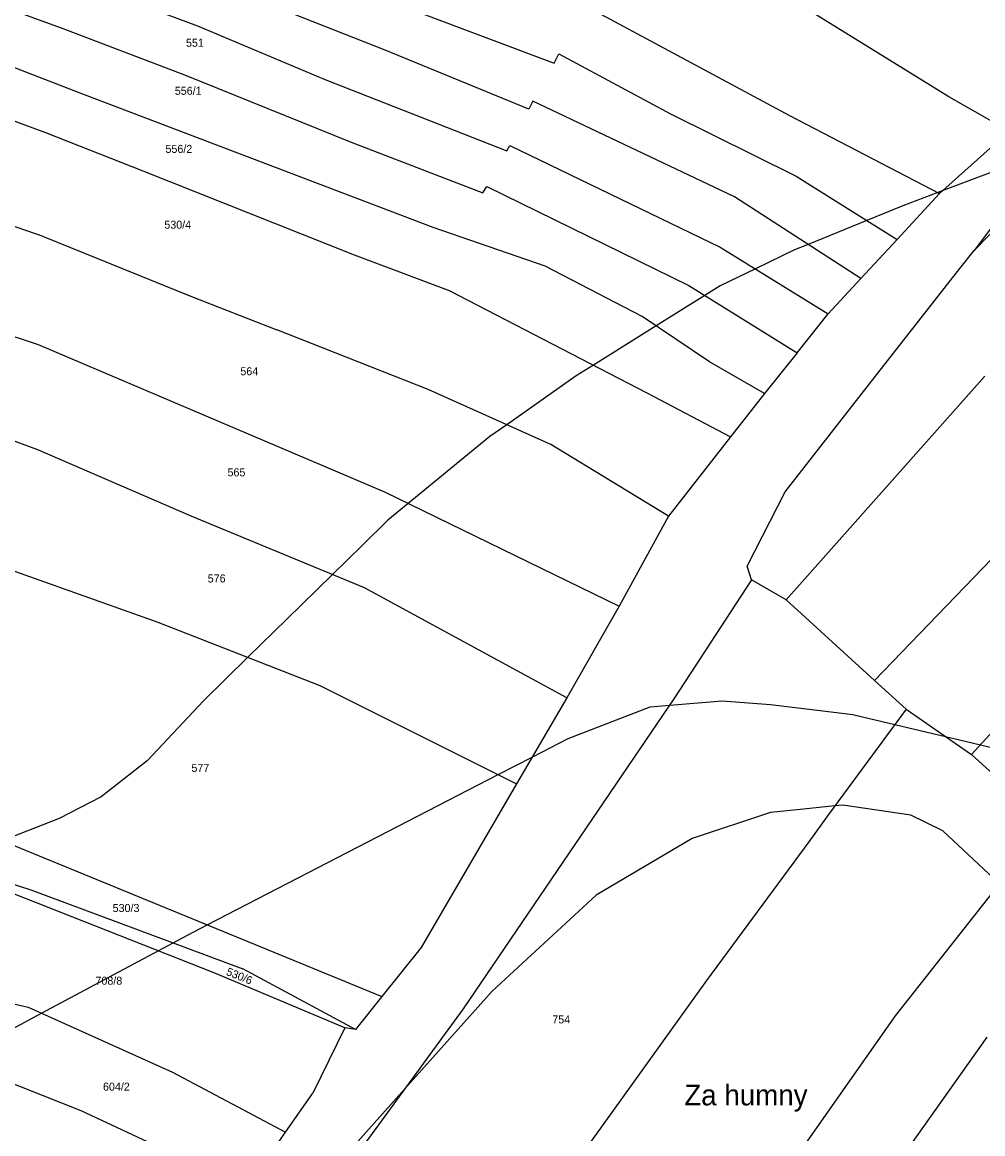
# Model space of a CAD drawing. Extents: x -749173 to -746119, y -1132678 to -1130338.
# Drawn here: x -748183 to -747979.1, y -1131207.1 to -1130971 of the extents above; entities that cross this region are included whole.
import ezdxf

# ---------------------------------------------------------------- set-up
doc = ezdxf.new("R2010")
doc.units = 0
for name, color, linetype in [('Vrstva 1', 7, 'Continuous'), ('Vrstva 15', 7, 'Continuous'), ('Vrstva 18', 7, 'Continuous'), ('Vrstva 52', 7, 'Continuous'), ('Vrstva 6', 7, 'Continuous')]:
    doc.layers.add(name, color=color, linetype=linetype)

msp = doc.modelspace()

# ---------------------------------------------------------------- linework, layer by layer
at = {"layer": 'Vrstva 1'}
for points in [[(-747973.45, -1130994.17), (-747988.29, -1131007.37)], [(-747968.09, -1131002.39), (-747980.93, -1131019.45)], [(-747980.93, -1131019.45), (-747967.89, -1131006.15)], [(-747988.29, -1131007.37), (-747997.28, -1131017.11)], [(-747997.28, -1131017.11), (-748004.94, -1131025.41)], [(-747983.97, -1131023.31), (-747980.93, -1131019.45)], [(-748004.94, -1131025.41), (-748011.89, -1131032.94)], [(-748001.36, -1131045.5), (-747983.97, -1131023.31)], [(-748018.5, -1131041.2), (-748011.89, -1131032.94)], [(-748018.5, -1131041.2), (-748025.45, -1131049.82)], [(-748021.05, -1131070.73), (-748001.36, -1131045.5)], [(-747978.68, -1131046.17), (-748020.82, -1131093.67)], [(-748025.45, -1131049.82), (-748032.6, -1131059.05)], [(-747916.37, -1131055.44), (-747981.47, -1131126.53)], [(-748032.6, -1131059.05), (-748045.79, -1131075.87)], [(-748029.08, -1131086.54), (-748021.05, -1131070.73)], [(-748045.79, -1131075.87), (-748056.24, -1131094.99)], [(-747973.31, -1131081.03), (-748002.07, -1131110.77)], [(-748028.17, -1131089.42), (-748029.08, -1131086.54)], [(-748028.17, -1131089.42), (-748044.49, -1131114.5)], [(-748020.82, -1131093.67), (-748028.17, -1131089.42)], [(-748002.07, -1131110.77), (-748020.82, -1131093.67)], [(-748056.24, -1131094.99), (-748067.39, -1131114.45)], [(-747995.36, -1131116.92), (-748002.07, -1131110.77)], [(-748044.49, -1131114.5), (-748089.38, -1131180.54)], [(-748067.39, -1131114.45), (-748078.05, -1131132.75)], [(-747995.36, -1131116.92), (-747981.47, -1131126.53)], [(-747968.37, -1131138.42), (-747981.47, -1131126.53)], [(-748078.05, -1131132.75), (-748098.31, -1131167.52)], [(-748142.12, -1131172.94), (-748200.11, -1131150.07)], [(-748098.31, -1131167.52), (-748106.65, -1131177.93)], [(-748114.48, -1131184.54), (-748142.12, -1131172.94)], [(-748106.65, -1131177.93), (-748112.26, -1131184.92)], [(-748089.38, -1131180.54), (-748114.45, -1131214.85)], [(-748114.48, -1131184.54), (-748121.26, -1131198.42)], [(-748112.26, -1131184.92), (-748114.48, -1131184.54)], [(-748127.06, -1131206.76), (-748121.26, -1131198.42)], [(-748130.99, -1131212.41), (-748127.06, -1131206.76)]]:
    msp.add_lwpolyline(points, dxfattribs=at)
at = {"layer": 'Vrstva 52'}
for points in [[(-747967.99, -1130999.4), (-747987.69, -1131006.84), (-747988.63, -1131007.19), (-747996.06, -1131010), (-748003.68, -1131013.1), (-748016.14, -1131018.18), (-748019.06, -1131019.37), (-748027.33, -1131023.38), (-748034.81, -1131027), (-748038.07, -1131029.03), (-748048.4, -1131035.5), (-748061.71, -1131043.83), (-748065.37, -1131046.12), (-748080.1, -1131056.48), (-748083.69, -1131059), (-748101.03, -1131073.19), (-748105.37, -1131076.75), (-748110.77, -1131082.04), (-748117.13, -1131088.27), (-748126.81, -1131097.77), (-748135.06, -1131105.87), (-748144.5, -1131115.12), (-748156.44, -1131127.87), (-748166.19, -1131135.5), (-748175.12, -1131140.12), (-748187.21, -1131144.83)], [(-748198.5, -1131192), (-748197.42, -1131191.42), (-748193.41, -1131189.27), (-748178.87, -1131181.48), (-748154.11, -1131168.21), (-748150.94, -1131166.51), (-748147.87, -1131164.87), (-748143.69, -1131162.71), (-748081.96, -1131130.79), (-748074.73, -1131127.06), (-748067.12, -1131123.12), (-748049.69, -1131116.37), (-748045.53, -1131116.03), (-748034.37, -1131115.12), (-748024.12, -1131115.87), (-748010.67, -1131117.51), (-748006.69, -1131118), (-748004.62, -1131118.49), (-747997.73, -1131120.13), (-747987.02, -1131122.69), (-747979.58, -1131124.46), (-747967.99, -1131127.23)], [(-747975.53, -1131153.99), (-747987.56, -1131142.75), (-747994.37, -1131139.37), (-748008.81, -1131137.25), (-748010.49, -1131137.43), (-748017.15, -1131138.13), (-748024.12, -1131138.87), (-748040.75, -1131144.37), (-748061.12, -1131156.37), (-748083.25, -1131176.75), (-748101.82, -1131197.57), (-748128.75, -1131227.75)]]:
    msp.add_lwpolyline(points, dxfattribs=at)
at = {"layer": 'Vrstva 6'}
for points in [[(-748188.9, -1130955.67), (-748145.76, -1130971.78)], [(-748105.93, -1130976.94), (-748156.11, -1130957.09)], [(-748203.98, -1130961.53), (-748174.74, -1130972.17)], [(-747986.3, -1130986.83), (-748025.01, -1130962.88)], [(-748065.85, -1130966.16), (-748020.12, -1130990.83)], [(-748170.66, -1130986.1), (-748215.31, -1130968.76)], [(-748099.08, -1130968.76), (-748070.08, -1130979.7)], [(-748174.74, -1130972.17), (-748148.5, -1130982.18)], [(-748145.76, -1130971.78), (-748118.89, -1130983.08)], [(-748075.44, -1130989.47), (-748105.93, -1130976.94)], [(-748070.08, -1130979.7), (-748069.08, -1130977.72)], [(-748069.08, -1130977.72), (-748045.37, -1130990.45)], [(-748148.5, -1130982.18), (-748113.18, -1130996.46)], [(-748118.89, -1130983.08), (-748080.1, -1130998.3)], [(-748197.86, -1130987.14), (-748178.05, -1130994.42)], [(-748095.78, -1131014.6), (-748170.66, -1130986.1)], [(-747973.45, -1130994.17), (-747986.3, -1130986.83)], [(-748074.61, -1130987.79), (-748075.44, -1130989.47)], [(-748031.76, -1131008.11), (-748074.61, -1130987.79)], [(-748045.37, -1130990.45), (-748018.68, -1131003.71)], [(-748020.12, -1130990.83), (-747988.29, -1131007.37)], [(-748178.05, -1130994.42), (-748157.35, -1131002.56)], [(-748113.18, -1130996.46), (-748085.2, -1131007.26)], [(-748080.1, -1130998.3), (-748079.5, -1130997.21)], [(-748079.5, -1130997.21), (-748034.8, -1131018.75)], [(-748157.35, -1131002.56), (-748112.55, -1131020.43)], [(-748018.68, -1131003.71), (-747997.28, -1131017.11)], [(-748085.2, -1131007.26), (-748084.35, -1131005.87)], [(-748084.35, -1131005.87), (-748041.45, -1131026.93)], [(-748178.35, -1131016.55), (-748204.79, -1131007.48)], [(-748004.94, -1131025.41), (-748031.76, -1131008.11)], [(-748071.94, -1131022.78), (-748095.78, -1131014.6)], [(-748178.35, -1131016.55), (-748147.39, -1131029.12)], [(-748112.55, -1131020.43), (-748092.33, -1131027.98)], [(-748034.8, -1131018.75), (-748011.89, -1131032.94)], [(-748051.38, -1131033.51), (-748071.94, -1131022.78)], [(-748217.06, -1131027.07), (-748179.59, -1131039.45)], [(-748041.45, -1131026.93), (-748018.5, -1131041.2)], [(-748147.39, -1131029.12), (-748128.96, -1131036.36)], [(-748092.33, -1131027.98), (-748050.36, -1131049.71)], [(-748037.07, -1131043.09), (-748051.38, -1131033.51)], [(-748096.79, -1131049.01), (-748128.96, -1131036.36)], [(-748179.59, -1131039.45), (-748106.1, -1131070.73)], [(-748025.45, -1131049.82), (-748037.07, -1131043.09)], [(-748179.65, -1131061.85), (-748215.75, -1131048.5)], [(-748070.74, -1131060.67), (-748096.79, -1131049.01)], [(-748050.36, -1131049.71), (-748032.6, -1131059.05)], [(-748045.79, -1131075.87), (-748070.74, -1131060.67)], [(-748147.12, -1131075.88), (-748179.65, -1131061.85)], [(-748106.1, -1131070.73), (-748056.24, -1131094.99)], [(-748110.29, -1131091.1), (-748147.12, -1131075.88)], [(-748200.15, -1131082.03), (-748154.2, -1131098.38)], [(-748067.39, -1131114.45), (-748110.29, -1131091.1)], [(-748154.2, -1131098.38), (-748119.78, -1131111.85)], [(-748119.78, -1131111.85), (-748078.05, -1131132.75)], [(-747995.36, -1131116.92), (-748011.86, -1131139.28)], [(-748199.59, -1131139.75), (-748106.65, -1131177.93)], [(-748011.86, -1131139.28), (-748016.02, -1131145.05)], [(-747997.58, -1131182.04), (-747965.44, -1131141.16)], [(-748016.02, -1131145.05), (-748037.76, -1131174.55)], [(-748200.06, -1131149.14), (-748181.16, -1131155.26)], [(-748181.16, -1131155.26), (-748136.15, -1131172.02)], [(-748112.26, -1131184.92), (-748136.15, -1131172.02)], [(-748198.94, -1131176.25), (-748181.72, -1131180.2)], [(-748037.76, -1131174.55), (-748063.48, -1131210.43)], [(-748181.72, -1131180.2), (-748151.08, -1131194.02)], [(-748024.52, -1131220.29), (-747997.58, -1131182.04)], [(-747978.25, -1131186.55), (-747998.39, -1131214.99)], [(-748191.48, -1131193.81), (-748170.55, -1131202.15)], [(-748151.08, -1131194.02), (-748127.06, -1131206.76)], [(-748170.55, -1131202.15), (-748152.1, -1131210.73)]]:
    msp.add_lwpolyline(points, dxfattribs=at)

# ---------------------------------------------------------------- texts
at = {"layer": 'Vrstva 15'}
msp.add_text('Za humny', height=4.4, dxfattribs=at).set_placement((-748042.44, -1131201.04))
at = {"layer": 'Vrstva 18'}
for s, p in [('551', (-748148.21, -1130976.21)), ('556/1', (-748150.59, -1130986.41)), ('556/2', (-748152.57, -1130998.75)), ('530/4', (-748152.81, -1131014.85)), ('564', (-748136.67, -1131045.98)), ('565', (-748139.4, -1131067.44)), ('576', (-748143.6, -1131089.98)), ('577', (-748147.06, -1131130.22)), ('530/3', (-748163.78, -1131159.97)), ('708/8', (-748167.43, -1131175.41)), ('754', (-748070.46, -1131183.63)), ('604/2', (-748165.83, -1131197.91))]:
    msp.add_text(s, height=1.7, dxfattribs=at).set_placement(p)
msp.add_text('530/6', height=1.7, rotation=338.0272, dxfattribs=at).set_placement((-748139.82, -1131173.29))

doc.saveas('drawing.dxf')
